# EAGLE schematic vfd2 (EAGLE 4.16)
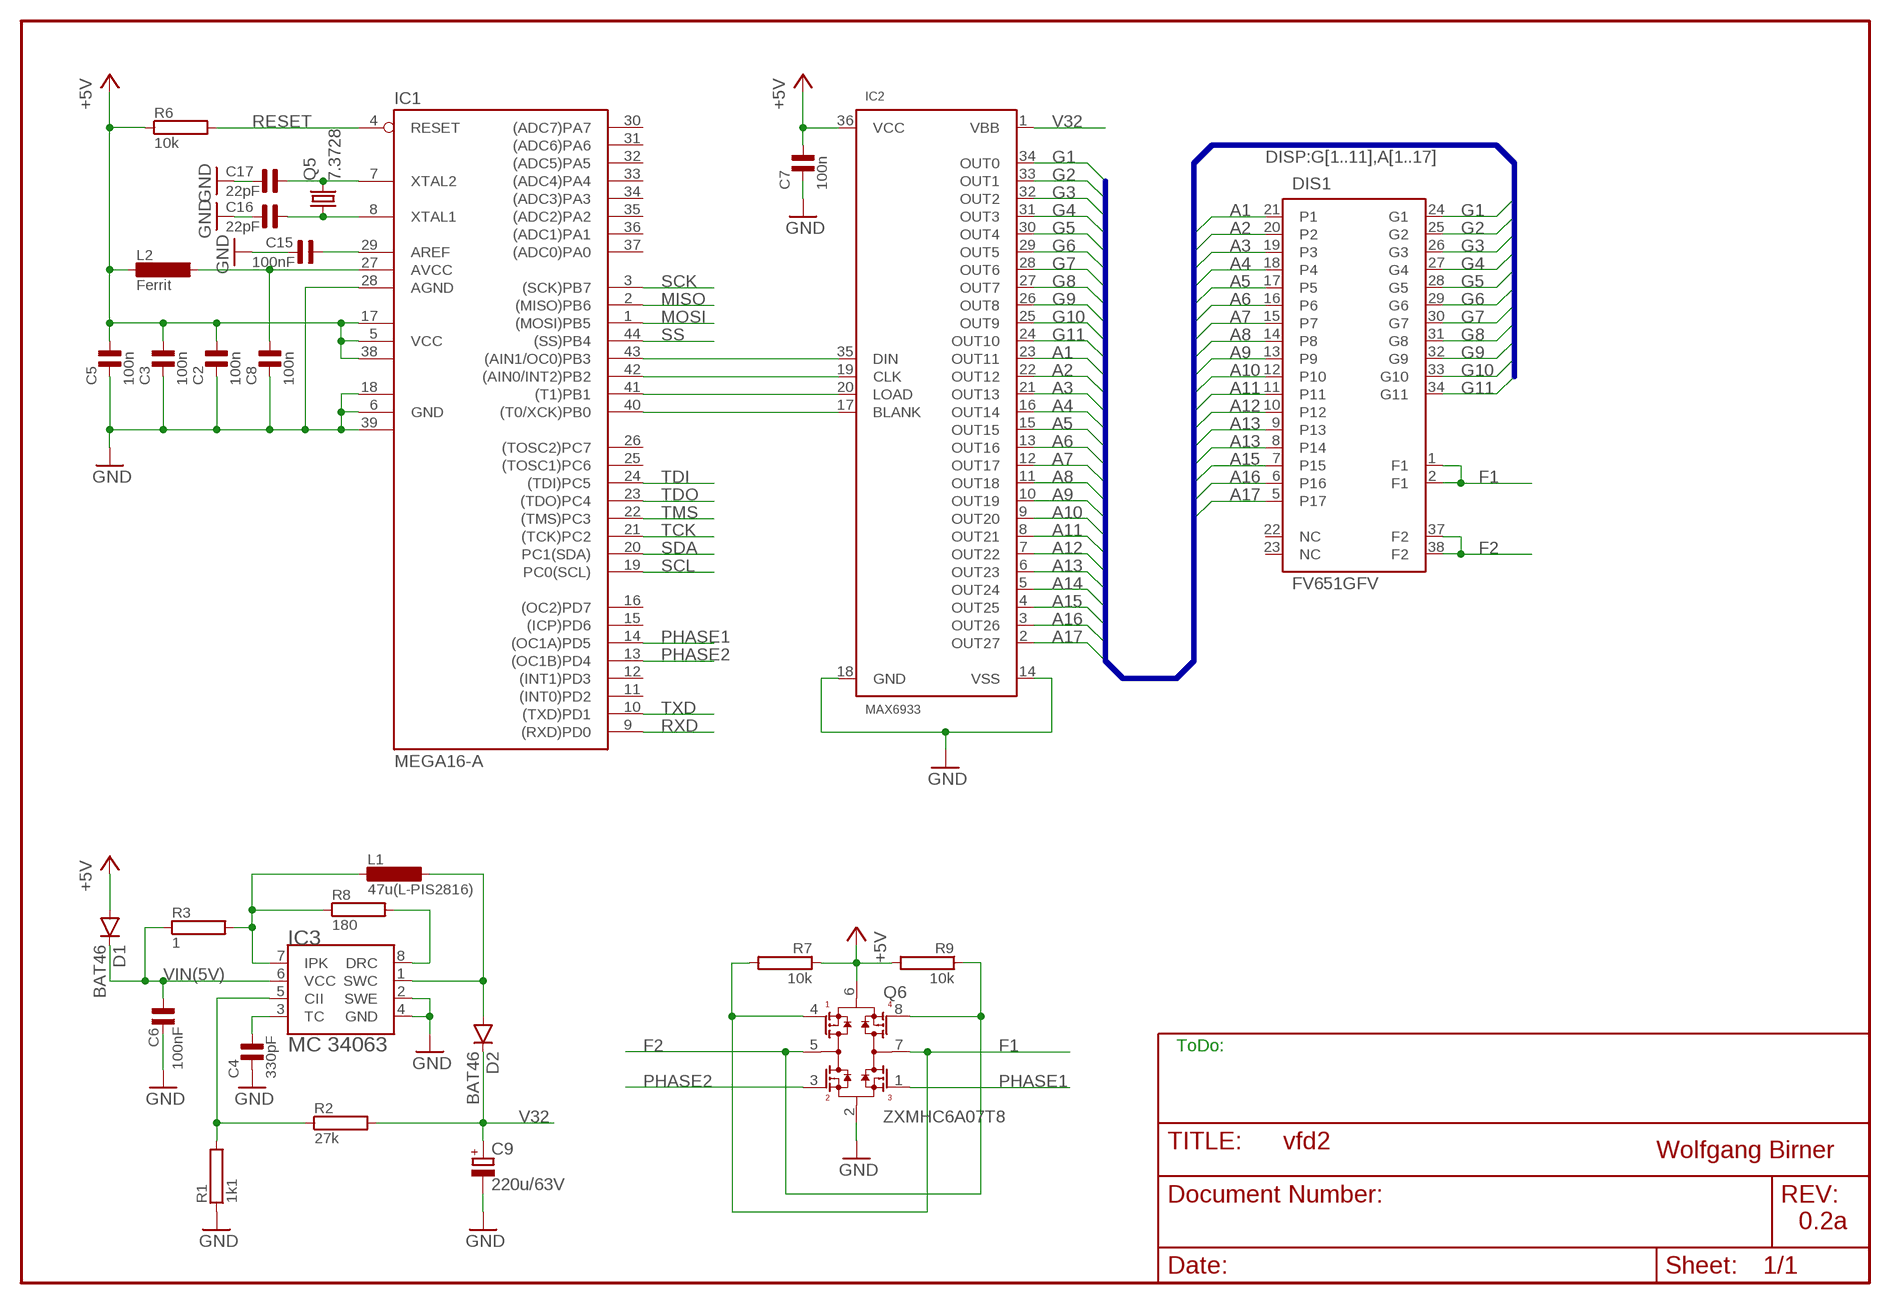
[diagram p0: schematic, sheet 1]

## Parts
C2  100n  C0805  [0805]
C3  100n  C0805  [0805]
C4  330pF  C0805  [0805]
C5  100n  C0805  [0805]
C6  100nF  C0805  [0805]
C7  100n  C0805  [0805]
C8  100n  C0805  [0805]
C9  220u/63V  CPOL-EUE5-G10X20  [E5-G10X20]
C15  100nF  C0805  [0805]
C16  22pF  C0805  [0805]
C17  22pF  C0805  [0805]
D1  BAT46  DIODE"  [MINIMELF]
D2  BAT46  DIODE"  [MINIMELF]
DIS1  FV651GFV  FV651G*  [FV651G]
IC1  MEGA16-A  [TQFP44]
IC2  MAX6933  [SSOP36L]
IC3  MC34063  [SO08]
L1  47u(L-PIS2816)  LPIS2816  [PIS2816]
L2  Ferrit  L0805  [0805]
Q5  7.3728  CRYTALHC49S  [HC49/S]
Q6  ZXMHC6A07T8  [SM8]
R1  1k1  R0805  [0805]
R2  27k  R0805  [0805]
R3  1  R0805  [0805]
R6  10k  R0805  [0805]
R7  10k  R0805  [0805]
R8  180  R0805  [0805]
R9  10k  R0805  [0805]

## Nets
+5V: C2.2 C3.2 C5.2 C7.2 D1.A IC1.5(VCC) IC1.17(VCC1) IC1.38(VCC2) IC2.36(VCC) L2.1 Q6.6(S1,S4) R6.1 R7.1 R9.2
A1: DIS1.21(P1) IC2.23(OUT11)
A2: DIS1.20(P2) IC2.22(OUT12)
A3: DIS1.19(P3) IC2.21(OUT13)
A4: DIS1.18(P4) IC2.16(OUT14)
A5: DIS1.17(P5) IC2.15(OUT15)
A6: DIS1.16(P6) IC2.13(OUT16)
A7: DIS1.15(P7) IC2.12(OUT17)
A8: DIS1.14(P8) IC2.11(OUT18)
A9: DIS1.13(P9) IC2.10(OUT19)
A10: DIS1.12(P10) IC2.9(OUT20)
A11: DIS1.11 IC2.8(OUT21)
A12: DIS1.10(P12) IC2.7(OUT22)
A13: DIS1.8(P14) DIS1.9(P13) IC2.6(OUT23)
A14: IC2.5(OUT24)
A15: DIS1.7(P15) IC2.4(OUT25)
A16: DIS1.6(P16) IC2.3(OUT26)
A17: DIS1.5(P17) IC2.2(OUT27)
F1: DIS1.1(F1) DIS1.2(F1) Q6.4(G1) Q6.7(D3,D4) R7.2
F2: DIS1.37(F2) DIS1.38(F2) Q6.5(D1,D2) Q6.8(G4) R9.1
G1: DIS1.24(G1) IC2.34(OUT0)
G2: DIS1.25(G2) IC2.33(OUT1)
G3: DIS1.26(G3) IC2.32(OUT2)
G4: DIS1.27(G4) IC2.31(OUT3)
G5: DIS1.28(G5) IC2.30(OUT4)
G6: DIS1.29(G6) IC2.29(OUT5)
G7: DIS1.30(G7) IC2.28(OUT6)
G8: DIS1.31(G8) IC2.27(OUT7)
G9: DIS1.32(G9) IC2.26(OUT8)
G10: DIS1.33(G10) IC2.25(OUT9)
G11: DIS1.34(G11) IC2.24(OUT10)
GND [gnd]: C2.1 C3.1 C4.1 C5.1 C6.1 C7.1 C8.1 C9.- C15.1 C16.1 C17.1 IC1.6(GND) IC1.18(GND1) IC1.28(AGND) IC1.39(GND2) IC2.14(VSS) IC2.18(GND) IC3.2(SWE) IC3.4(GND) Q6.2(S2,S3) R1.1
MISO: IC1.2((MISO)PB6)
MOSI: IC1.1((MOSI)PB5)
N$1: C4.2 IC3.3(TC)
N$2: IC3.8(DRC) R8.2
N$3: D2.A IC3.1(SWC) L1.2
N$4: IC3.7(IPK) L1.1 R3.2 R8.1
N$5: IC3.5(CII) R1.2 R2.1
N$6: C15.2 IC1.29(AREF)
N$19: C17.2 IC1.7(XTAL2) Q5.2
N$21: C8.2 IC1.27(AVCC) L2.2
N$22: C16.2 IC1.8(XTAL1) Q5.1
N$23: IC1.43((AIN1/OC0)PB3) IC2.35(DIN)
N$24: IC1.42((AIN0/INT2)PB2) IC2.19(CLK)
N$25: IC1.41((T1)PB1) IC2.20(LOAD)
N$26: IC1.40((T0/XCK)PB0) IC2.17(BLANK)
PHASE1: IC1.14((OC1A)PD5) Q6.1(G3)
PHASE2: IC1.13((OC1B)PD4) Q6.3(G2)
RESET: IC1.4(RESET) R6.2
RXD: IC1.9((RXD)PD0)
SCK: IC1.3((SCK)PB7)
SCL: IC1.19(PC0(SCL))
SDA: IC1.20(PC1(SDA))
SS: IC1.44((SS)PB4)
TCK: IC1.21((TCK)PC2)
TDI: IC1.24((TDI)PC5)
TDO: IC1.23((TDO)PC4)
TMS: IC1.22((TMS)PC3)
TXD: IC1.10((TXD)PD1)
V32 [supply]: C9.+ D2.K(C) IC2.1(VBB) R2.2
VIN(5V) [supply]: C6.2 D1.K(C) IC3.6(VCC) R3.1
Unconnected: DIS1.22(NC) DIS1.23(NC) IC1.11((INT0)PD2) IC1.12((INT1)PD3) IC1.15((ICP)PD6) IC1.16((OC2)PD7) IC1.25((TOSC1)PC6) IC1.26((TOSC2)PC7) IC1.30((ADC7)PA7) IC1.31((ADC6)PA6) IC1.32((ADC5)PA5) IC1.33((ADC4)PA4) IC1.34((ADC3)PA3) IC1.35((ADC2)PA2) IC1.36((ADC1)PA1) IC1.37((ADC0)PA0)

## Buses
DISP:G[1..11],A[1..17]

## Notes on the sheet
- ToDo:
- Wolfgang Birner
- 0.2a

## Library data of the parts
C2-C8 C15-C17 = bluoss-elektronik:C: Capacitor
C9 = WB:CPOL-EU: POLARIZED CAPACITOR, European symbol
D1 D2 = bluoss-elektronik:DIODE: Diode
DIS1 = WB:FV651G
IC1 = atmel:MEGA16: MICROCONTROLLER 16 Kbytes FLASH 1 kbytes SRAM 512 bytes EEPROM USART 8-channel 10 bit ADC Source: avr.lbr
IC2 = wb-ic:MAX6933
IC3 = bluoss-elektronik:MC34063
L1 L2 = bluoss-elektronik:L: Inductance
Q5 = crystal:CRYTAL: CRYSTAL
Q6 = wb-ic:ZXMHC6A07T8: Zetex H-Bridge MOSFET 2xN 2xP (Reichelt: ZXMHC 6A07 T8TA)
R1-R3 R6-R9 = bluoss-elektronik:R: Resistor

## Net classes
0 default: width 0.203 mm, drill 0.203 mm, clearance 0.305 mm
1 supply: width 0.203 mm, drill 0.203 mm, clearance 0.305 mm
2 gnd: width 0.203 mm, drill 0.203 mm, clearance 0.305 mm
